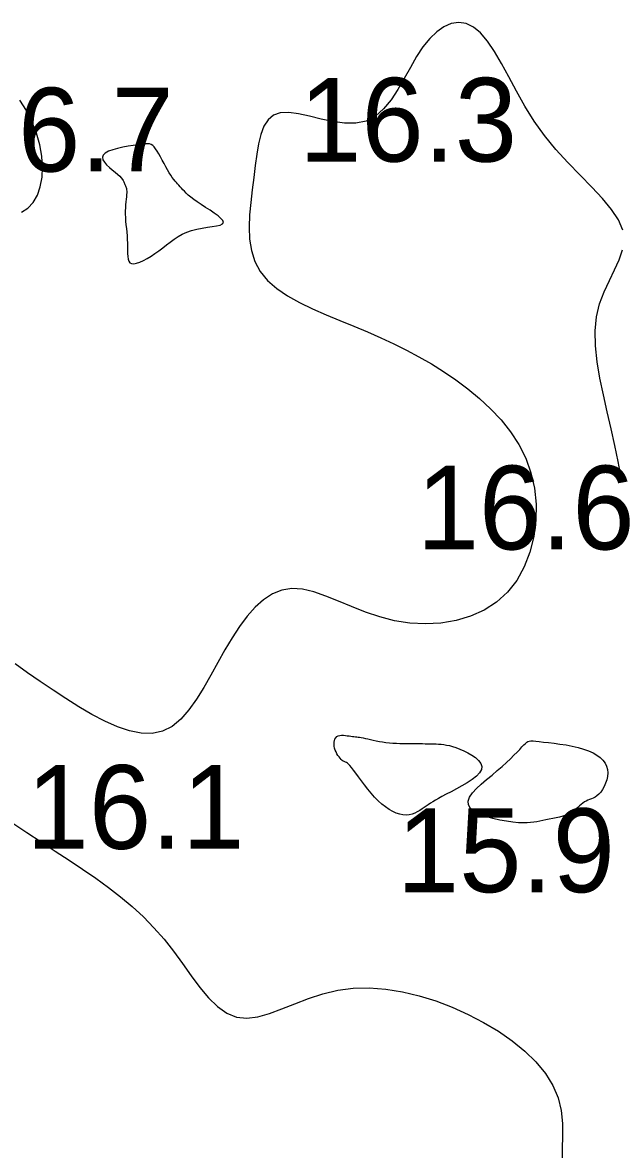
# Model space of a CAD drawing. Extents: x 3040093 to 3056816, y 408076 to 509144.
# Drawn here: x 3045671.3 to 3045706.9, y 434480.9 to 434548.2 of the extents above; entities that cross this region are included whole.
import ezdxf

# ---------------------------------------------------------------- set-up
doc = ezdxf.new("R2010")
doc.units = 0
doc.layers.add('V-CHAN-CONT-EL17', color=7, linetype='Continuous')
doc.layers.add('V-TOPO-SOUN-0610', color=7, linetype='Continuous')

msp = doc.modelspace()

# ---------------------------------------------------------------- linework, layer by layer
at = {"layer": 'V-CHAN-CONT-EL17'}
for points in [[(3045707.132, 434535.799), (3045706.878, 434536.408), (3045706.463, 434537.038), (3045705.921, 434537.692), (3045705.285, 434538.373), (3045704.588, 434539.086), (3045703.863, 434539.834), (3045703.145, 434540.619), (3045702.465, 434541.447), (3045701.85, 434542.315), (3045701.297, 434543.203), (3045700.794, 434544.088), (3045700.33, 434544.943), (3045699.895, 434545.745), (3045699.478, 434546.469), (3045699.067, 434547.089), (3045698.652, 434547.582), (3045698.225, 434547.928), (3045697.787, 434548.13), (3045697.343, 434548.195), (3045696.899, 434548.131), (3045696.458, 434547.946), (3045696.026, 434547.648), (3045695.608, 434547.245), (3045695.208, 434546.745), (3045694.828, 434546.159), (3045694.46, 434545.516), (3045694.091, 434544.85), (3045693.709, 434544.193), (3045693.302, 434543.577), (3045692.859, 434543.036), (3045692.366, 434542.603), (3045691.814, 434542.309), (3045691.194, 434542.177), (3045690.524, 434542.179), (3045689.825, 434542.276), (3045689.12, 434542.428), (3045688.432, 434542.596), (3045687.782, 434542.742), (3045687.192, 434542.825), (3045686.685, 434542.807), (3045686.276, 434542.658), (3045685.957, 434542.383), (3045685.714, 434541.998), (3045685.531, 434541.517), (3045685.394, 434540.955), (3045685.288, 434540.328), (3045685.198, 434539.65), (3045685.11, 434538.937), (3045685.014, 434538.202), (3045684.923, 434537.457), (3045684.854, 434536.712), (3045684.827, 434535.976), (3045684.858, 434535.26), (3045684.966, 434534.575), (3045685.168, 434533.93), (3045685.483, 434533.335), (3045685.923, 434532.797), (3045686.475, 434532.312), (3045687.12, 434531.872), (3045687.839, 434531.468), (3045688.613, 434531.093), (3045689.424, 434530.738), (3045690.252, 434530.396), (3045691.079, 434530.059), (3045691.889, 434529.718), (3045692.682, 434529.37), (3045693.458, 434529.009), (3045694.22, 434528.631), (3045694.969, 434528.231), (3045695.708, 434527.805), (3045696.438, 434527.349), (3045697.162, 434526.857), (3045697.879, 434526.326), (3045698.577, 434525.752), (3045699.245, 434525.135), (3045699.868, 434524.472), (3045700.434, 434523.76), (3045700.929, 434522.997), (3045701.34, 434522.182), (3045701.654, 434521.312), (3045701.86, 434520.389), (3045701.956, 434519.431), (3045701.943, 434518.46), (3045701.822, 434517.498), (3045701.592, 434516.567), (3045701.255, 434515.688), (3045700.81, 434514.884), (3045700.26, 434514.176), (3045699.606, 434513.583), (3045698.864, 434513.105), (3045698.051, 434512.739), (3045697.182, 434512.481), (3045696.277, 434512.329), (3045695.351, 434512.278), (3045694.423, 434512.326), (3045693.508, 434512.469), (3045692.622, 434512.7), (3045691.767, 434512.992), (3045690.947, 434513.317), (3045690.16, 434513.645), (3045689.409, 434513.946), (3045688.695, 434514.191), (3045688.018, 434514.349), (3045687.379, 434514.392), (3045686.78, 434514.297), (3045686.217, 434514.07), (3045685.686, 434513.727), (3045685.183, 434513.279), (3045684.705, 434512.743), (3045684.248, 434512.131), (3045683.808, 434511.458), (3045683.381, 434510.738), (3045682.963, 434509.986), (3045682.547, 434509.226), (3045682.125, 434508.482), (3045681.69, 434507.779), (3045681.234, 434507.142), (3045680.748, 434506.595), (3045680.226, 434506.164), (3045679.66, 434505.873), (3045679.045, 434505.739), (3045678.385, 434505.752), (3045677.688, 434505.891), (3045676.96, 434506.138), (3045676.209, 434506.474), (3045675.443, 434506.88), (3045674.668, 434507.338), (3045673.891, 434507.827), (3045673.119, 434508.332), (3045672.355, 434508.847), (3045671.6, 434509.368), (3045670.855, 434509.892)], [(3045671.24, 434536.866), (3045671.622, 434537.112), (3045671.937, 434537.452), (3045672.183, 434537.88), (3045672.359, 434538.384), (3045672.463, 434538.951), (3045672.494, 434539.567), (3045672.451, 434540.22), (3045672.332, 434540.898), (3045672.136, 434541.588), (3045671.864, 434542.275), (3045671.526, 434542.941), (3045671.133, 434543.565)], [(3045707.036, 434521.034), (3045706.867, 434521.978), (3045706.671, 434522.946), (3045706.447, 434523.939), (3045706.21, 434524.946), (3045705.978, 434525.956), (3045705.771, 434526.957), (3045705.607, 434527.936), (3045705.506, 434528.882), (3045705.486, 434529.782), (3045705.566, 434530.625), (3045705.756, 434531.401), (3045706.025, 434532.119), (3045706.336, 434532.789), (3045706.648, 434533.422), (3045706.923, 434534.028), (3045707.121, 434534.62)], [(3045670.719, 434500.39), (3045671.557, 434499.82), (3045672.404, 434499.262), (3045673.248, 434498.714), (3045674.079, 434498.174), (3045674.887, 434497.636), (3045675.67, 434497.096), (3045676.425, 434496.547), (3045677.151, 434495.983), (3045677.848, 434495.399), (3045678.514, 434494.787), (3045679.147, 434494.142), (3045679.746, 434493.458), (3045680.312, 434492.734), (3045680.852, 434491.994), (3045681.376, 434491.265), (3045681.893, 434490.577), (3045682.411, 434489.959), (3045682.941, 434489.438), (3045683.492, 434489.044), (3045684.073, 434488.806), (3045684.692, 434488.741), (3045685.35, 434488.824), (3045686.047, 434489.02), (3045686.783, 434489.29), (3045687.559, 434489.601), (3045688.373, 434489.915), (3045689.226, 434490.197), (3045690.117, 434490.41), (3045691.046, 434490.525), (3045692.004, 434490.542), (3045692.984, 434490.467), (3045693.977, 434490.308), (3045694.973, 434490.072), (3045695.966, 434489.764), (3045696.946, 434489.392), (3045697.904, 434488.963), (3045698.831, 434488.482), (3045699.714, 434487.955), (3045700.538, 434487.383), (3045701.289, 434486.771), (3045701.953, 434486.121), (3045702.515, 434485.438), (3045702.961, 434484.725), (3045703.277, 434483.984), (3045703.457, 434483.222), (3045703.531, 434482.453), (3045703.539, 434481.692), (3045703.52, 434480.957), (3045703.513, 434480.263)]]:
    msp.add_lwpolyline(points, dxfattribs=at)
for points in [[(3045677.566, 434534.803), (3045677.565, 434534.594), (3045677.567, 434534.399), (3045677.577, 434534.221), (3045677.602, 434534.067), (3045677.645, 434533.942), (3045677.714, 434533.851), (3045677.814, 434533.799), (3045677.948, 434533.791), (3045678.113, 434533.822), (3045678.303, 434533.888), (3045678.513, 434533.984), (3045678.738, 434534.106), (3045678.971, 434534.247), (3045679.207, 434534.404), (3045679.442, 434534.571), (3045679.67, 434534.743), (3045679.895, 434534.917), (3045680.12, 434535.089), (3045680.349, 434535.254), (3045680.587, 434535.41), (3045680.838, 434535.551), (3045681.106, 434535.675), (3045681.394, 434535.778), (3045681.704, 434535.857), (3045682.023, 434535.917), (3045682.338, 434535.965), (3045682.631, 434536.007), (3045682.888, 434536.051), (3045683.095, 434536.102), (3045683.235, 434536.167), (3045683.293, 434536.253), (3045683.26, 434536.365), (3045683.147, 434536.499), (3045682.971, 434536.65), (3045682.748, 434536.813), (3045682.495, 434536.983), (3045682.229, 434537.155), (3045681.967, 434537.324), (3045681.726, 434537.485), (3045681.517, 434537.633), (3045681.342, 434537.769), (3045681.194, 434537.894), (3045681.069, 434538.009), (3045680.964, 434538.115), (3045680.872, 434538.213), (3045680.79, 434538.305), (3045680.713, 434538.391), (3045680.637, 434538.474), (3045680.561, 434538.555), (3045680.483, 434538.639), (3045680.404, 434538.729), (3045680.323, 434538.829), (3045680.238, 434538.942), (3045680.149, 434539.071), (3045680.055, 434539.22), (3045679.957, 434539.391), (3045679.854, 434539.579), (3045679.75, 434539.775), (3045679.644, 434539.975), (3045679.539, 434540.17), (3045679.437, 434540.355), (3045679.338, 434540.521), (3045679.246, 434540.662), (3045679.158, 434540.773), (3045679.071, 434540.855), (3045678.978, 434540.91), (3045678.871, 434540.943), (3045678.744, 434540.956), (3045678.59, 434540.951), (3045678.402, 434540.931), (3045678.174, 434540.901), (3045677.902, 434540.861), (3045677.601, 434540.812), (3045677.286, 434540.752), (3045676.974, 434540.682), (3045676.684, 434540.601), (3045676.432, 434540.508), (3045676.234, 434540.401), (3045676.108, 434540.281), (3045676.066, 434540.148), (3045676.098, 434540.004), (3045676.188, 434539.853), (3045676.321, 434539.699), (3045676.482, 434539.546), (3045676.655, 434539.397), (3045676.826, 434539.257), (3045676.979, 434539.129), (3045677.101, 434539.015), (3045677.195, 434538.916), (3045677.264, 434538.83), (3045677.314, 434538.754), (3045677.349, 434538.687), (3045677.372, 434538.629), (3045677.39, 434538.576), (3045677.406, 434538.528), (3045677.423, 434538.482), (3045677.443, 434538.437), (3045677.462, 434538.389), (3045677.481, 434538.337), (3045677.497, 434538.277), (3045677.509, 434538.208), (3045677.517, 434538.126), (3045677.518, 434538.029), (3045677.512, 434537.916), (3045677.501, 434537.786), (3045677.486, 434537.642), (3045677.47, 434537.485), (3045677.455, 434537.315), (3045677.442, 434537.135), (3045677.435, 434536.945), (3045677.434, 434536.747), (3045677.442, 434536.543), (3045677.456, 434536.333), (3045677.475, 434536.118), (3045677.497, 434535.901), (3045677.519, 434535.681), (3045677.539, 434535.46), (3045677.554, 434535.239), (3045677.564, 434535.02)], [(3045692.113, 434502.172), (3045691.91, 434502.417), (3045691.715, 434502.666), (3045691.531, 434502.911), (3045691.36, 434503.146), (3045691.204, 434503.361), (3045691.066, 434503.551), (3045690.946, 434503.707), (3045690.846, 434503.824), (3045690.765, 434503.907), (3045690.697, 434503.963), (3045690.64, 434504), (3045690.59, 434504.024), (3045690.543, 434504.042), (3045690.496, 434504.061), (3045690.446, 434504.09), (3045690.388, 434504.132), (3045690.326, 434504.189), (3045690.26, 434504.259), (3045690.194, 434504.34), (3045690.13, 434504.431), (3045690.069, 434504.531), (3045690.015, 434504.638), (3045689.969, 434504.75), (3045689.934, 434504.867), (3045689.91, 434504.985), (3045689.899, 434505.101), (3045689.901, 434505.212), (3045689.917, 434505.316), (3045689.949, 434505.408), (3045689.996, 434505.487), (3045690.061, 434505.549), (3045690.142, 434505.591), (3045690.238, 434505.617), (3045690.344, 434505.629), (3045690.458, 434505.629), (3045690.574, 434505.621), (3045690.69, 434505.608), (3045690.803, 434505.592), (3045690.907, 434505.577), (3045691.002, 434505.565), (3045691.088, 434505.555), (3045691.171, 434505.546), (3045691.253, 434505.537), (3045691.337, 434505.527), (3045691.427, 434505.514), (3045691.527, 434505.497), (3045691.64, 434505.475), (3045691.769, 434505.447), (3045691.912, 434505.414), (3045692.069, 434505.378), (3045692.238, 434505.34), (3045692.417, 434505.302), (3045692.605, 434505.266), (3045692.8, 434505.233), (3045693, 434505.205), (3045693.205, 434505.183), (3045693.412, 434505.166), (3045693.62, 434505.154), (3045693.829, 434505.145), (3045694.036, 434505.14), (3045694.24, 434505.137), (3045694.439, 434505.136), (3045694.633, 434505.135), (3045694.821, 434505.134), (3045695.002, 434505.133), (3045695.177, 434505.131), (3045695.347, 434505.129), (3045695.512, 434505.126), (3045695.673, 434505.122), (3045695.831, 434505.118), (3045695.986, 434505.111), (3045696.139, 434505.103), (3045696.292, 434505.092), (3045696.45, 434505.074), (3045696.614, 434505.048), (3045696.788, 434505.011), (3045696.975, 434504.96), (3045697.178, 434504.894), (3045697.4, 434504.811), (3045697.642, 434504.708), (3045697.89, 434504.586), (3045698.131, 434504.448), (3045698.349, 434504.296), (3045698.53, 434504.131), (3045698.659, 434503.955), (3045698.721, 434503.77), (3045698.702, 434503.579), (3045698.591, 434503.382), (3045698.401, 434503.184), (3045698.15, 434502.986), (3045697.855, 434502.792), (3045697.535, 434502.604), (3045697.206, 434502.426), (3045696.886, 434502.261), (3045696.594, 434502.11), (3045696.342, 434501.977), (3045696.129, 434501.859), (3045695.947, 434501.754), (3045695.79, 434501.659), (3045695.652, 434501.57), (3045695.525, 434501.486), (3045695.404, 434501.403), (3045695.281, 434501.318), (3045695.152, 434501.231), (3045695.015, 434501.143), (3045694.87, 434501.061), (3045694.716, 434500.987), (3045694.554, 434500.927), (3045694.383, 434500.886), (3045694.203, 434500.866), (3045694.015, 434500.875), (3045693.817, 434500.913), (3045693.613, 434500.982), (3045693.402, 434501.08), (3045693.187, 434501.204), (3045692.971, 434501.354), (3045692.753, 434501.527), (3045692.536, 434501.722), (3045692.322, 434501.938)], [(3045703.747, 434500.864), (3045703.561, 434500.801), (3045703.364, 434500.747), (3045703.16, 434500.7), (3045702.954, 434500.658), (3045702.749, 434500.62), (3045702.549, 434500.583), (3045702.359, 434500.546), (3045702.179, 434500.509), (3045702.004, 434500.472), (3045701.826, 434500.439), (3045701.635, 434500.414), (3045701.423, 434500.398), (3045701.182, 434500.395), (3045700.903, 434500.408), (3045700.578, 434500.44), (3045700.204, 434500.493), (3045699.796, 434500.568), (3045699.379, 434500.665), (3045698.974, 434500.783), (3045698.603, 434500.922), (3045698.288, 434501.083), (3045698.053, 434501.265), (3045697.919, 434501.469), (3045697.902, 434501.693), (3045697.989, 434501.934), (3045698.162, 434502.188), (3045698.402, 434502.452), (3045698.689, 434502.72), (3045699.004, 434502.991), (3045699.329, 434503.258), (3045699.644, 434503.519), (3045699.933, 434503.769), (3045700.195, 434504.007), (3045700.43, 434504.231), (3045700.639, 434504.437), (3045700.822, 434504.624), (3045700.981, 434504.791), (3045701.116, 434504.934), (3045701.228, 434505.052), (3045701.32, 434505.143), (3045701.399, 434505.21), (3045701.475, 434505.256), (3045701.557, 434505.282), (3045701.656, 434505.293), (3045701.781, 434505.29), (3045701.941, 434505.277), (3045702.145, 434505.256), (3045702.401, 434505.229), (3045702.7, 434505.197), (3045703.032, 434505.157), (3045703.386, 434505.109), (3045703.75, 434505.051), (3045704.114, 434504.983), (3045704.467, 434504.902), (3045704.798, 434504.809), (3045705.097, 434504.701), (3045705.363, 434504.579), (3045705.595, 434504.444), (3045705.792, 434504.296), (3045705.954, 434504.136), (3045706.08, 434503.965), (3045706.17, 434503.782), (3045706.223, 434503.589), (3045706.24, 434503.386), (3045706.224, 434503.178), (3045706.18, 434502.971), (3045706.113, 434502.769), (3045706.028, 434502.577), (3045705.929, 434502.4), (3045705.821, 434502.243), (3045705.709, 434502.112), (3045705.596, 434502.01), (3045705.485, 434501.932), (3045705.374, 434501.873), (3045705.266, 434501.827), (3045705.158, 434501.787), (3045705.053, 434501.749), (3045704.95, 434501.706), (3045704.85, 434501.652), (3045704.752, 434501.583), (3045704.654, 434501.501), (3045704.553, 434501.409), (3045704.447, 434501.312), (3045704.334, 434501.212), (3045704.209, 434501.114), (3045704.072, 434501.021), (3045703.918, 434500.937)]]:
    msp.add_lwpolyline(points, close=True, dxfattribs=at)

# ---------------------------------------------------------------- texts
at = {"layer": 'V-TOPO-SOUN-0610'}
for s, p in [('16.3 ', (3045687.813, 434539.89)), ('16.7 ', (3045667.313, 434539.3)), ('16.6 ', (3045694.833, 434516.73)), ('16.1 ', (3045671.543, 434498.85)), ('15.9 ', (3045693.653, 434496.26))]:
    msp.add_text(s, height=5, dxfattribs=at).set_placement(p)

doc.saveas('drawing.dxf')
